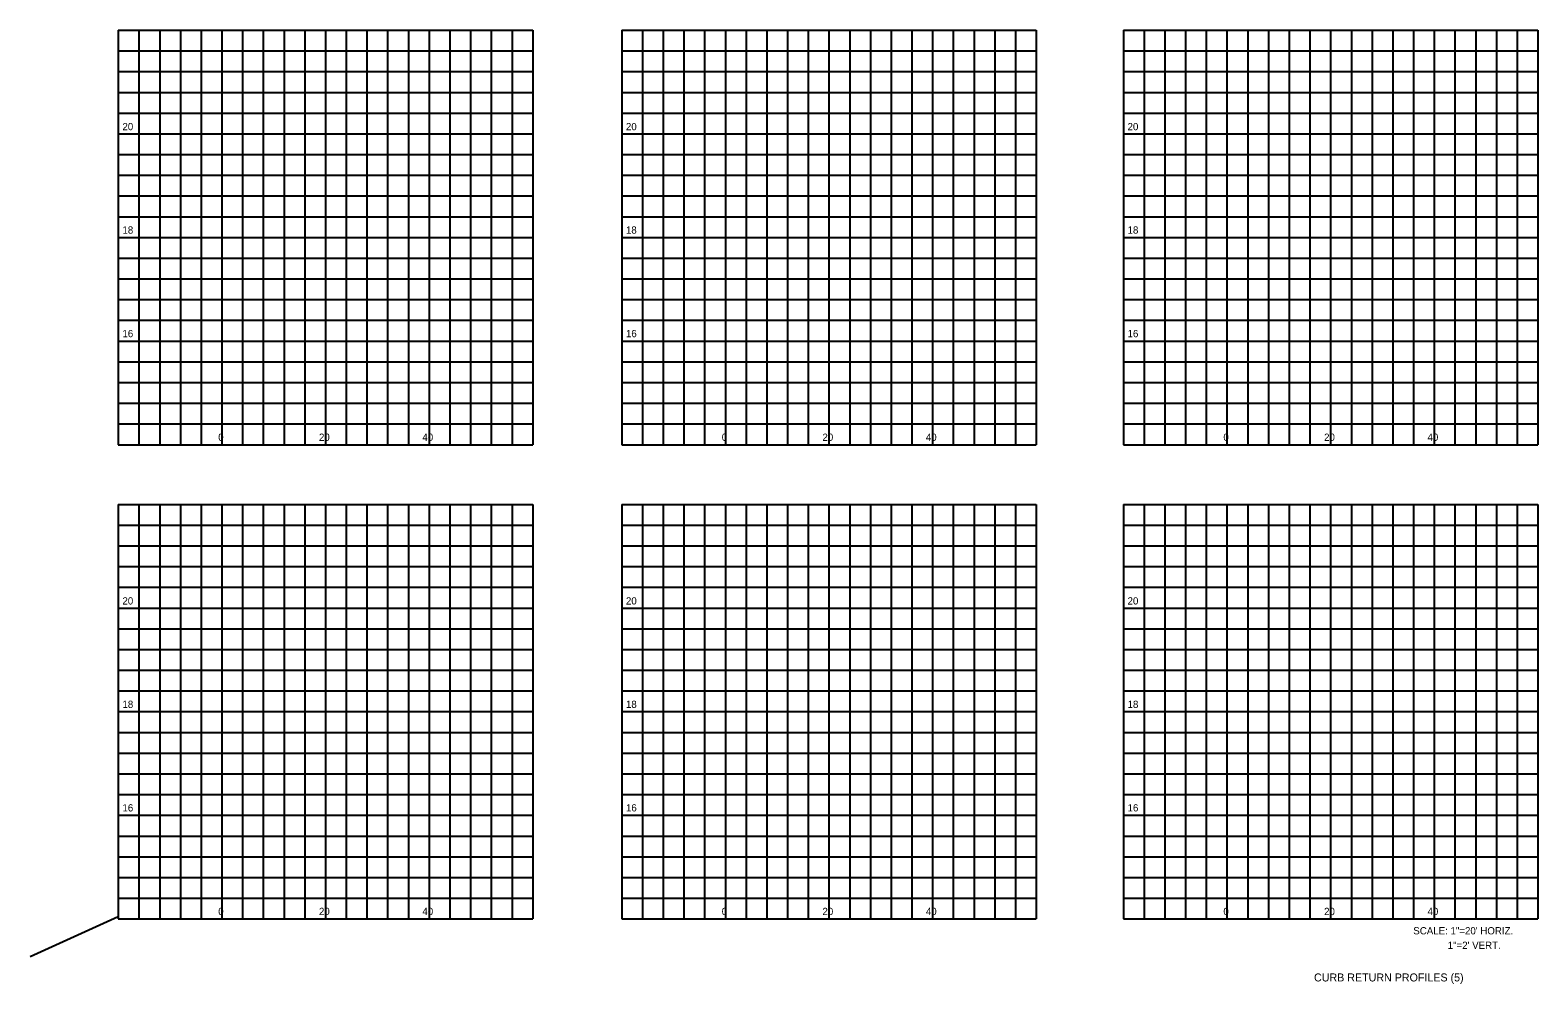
# Model space of a CAD drawing. Extents: x 127723 to 128378, y 21426 to 23736.
# Drawn here: x 127722.5 to 128013.5, y 22276.1 to 22460.2 of the extents above; entities that cross this region are included whole.
import ezdxf

# ---------------------------------------------------------------- set-up
doc = ezdxf.new("R2010")
doc.units = 0
for name, color, linetype in [('Default', 7, 'Continuous'), ('GroundCover', 7, 'Continuous'), ('Miscellaneous0', 7, 'Continuous'), ('SheetBorder_dp', 7, 'Continuous'), ('TextNotes', 7, 'Continuous')]:
    doc.layers.add(name, color=color, linetype=linetype)

msp = doc.modelspace()

# ---------------------------------------------------------------- linework, layer by layer
at = {"layer": 'Miscellaneous0'}
for p, q in [((127743.54, 22460.15), (127743.54, 22380.15)), ((127747.54, 22460.15), (127747.54, 22380.15)), ((127751.54, 22460.15), (127751.54, 22380.15)), ((127755.54, 22460.15), (127755.54, 22380.15)), ((127763.54, 22460.15), (127763.54, 22380.15)), ((127767.54, 22460.15), (127767.54, 22380.15)), ((127771.54, 22460.15), (127771.54, 22380.15)), ((127775.54, 22460.15), (127775.54, 22380.15)), ((127783.54, 22460.15), (127783.54, 22380.15)), ((127787.54, 22460.15), (127787.54, 22380.15)), ((127791.54, 22460.15), (127791.54, 22380.15)), ((127795.54, 22460.15), (127795.54, 22380.15)), ((127803.54, 22460.15), (127803.54, 22380.15)), ((127807.54, 22460.15), (127807.54, 22380.15)), ((127811.54, 22460.15), (127811.54, 22380.15)), ((127815.54, 22460.15), (127815.54, 22380.15)), ((127840.72, 22460.15), (127840.72, 22380.15)), ((127844.72, 22460.15), (127844.72, 22380.15)), ((127848.72, 22460.15), (127848.72, 22380.15)), ((127852.72, 22460.15), (127852.72, 22380.15)), ((127860.72, 22460.15), (127860.72, 22380.15)), ((127864.72, 22460.15), (127864.72, 22380.15)), ((127868.72, 22460.15), (127868.72, 22380.15)), ((127872.72, 22460.15), (127872.72, 22380.15)), ((127880.72, 22460.15), (127880.72, 22380.15)), ((127884.72, 22460.15), (127884.72, 22380.15)), ((127888.72, 22460.15), (127888.72, 22380.15)), ((127892.72, 22460.15), (127892.72, 22380.15)), ((127900.72, 22460.15), (127900.72, 22380.15)), ((127904.72, 22460.15), (127904.72, 22380.15)), ((127908.72, 22460.15), (127908.72, 22380.15)), ((127912.72, 22460.15), (127912.72, 22380.15)), ((127937.54, 22460.15), (127937.54, 22380.15)), ((127941.54, 22460.15), (127941.54, 22380.15)), ((127945.54, 22460.15), (127945.54, 22380.15)), ((127949.54, 22460.15), (127949.54, 22380.15)), ((127957.54, 22460.15), (127957.54, 22380.15)), ((127961.54, 22460.15), (127961.54, 22380.15)), ((127965.54, 22460.15), (127965.54, 22380.15)), ((127969.54, 22460.15), (127969.54, 22380.15)), ((127977.54, 22460.15), (127977.54, 22380.15)), ((127981.54, 22460.15), (127981.54, 22380.15)), ((127985.54, 22460.15), (127985.54, 22380.15)), ((127989.54, 22460.15), (127989.54, 22380.15)), ((127997.54, 22460.15), (127997.54, 22380.15)), ((128001.54, 22460.15), (128001.54, 22380.15)), ((128005.54, 22460.15), (128005.54, 22380.15)), ((128009.54, 22460.15), (128009.54, 22380.15)), ((127739.54, 22456.15), (127819.54, 22456.15)), ((127836.72, 22456.15), (127916.72, 22456.15)), ((127933.54, 22456.15), (128013.54, 22456.15)), ((127739.54, 22452.15), (127819.54, 22452.15)), ((127836.72, 22452.15), (127916.72, 22452.15)), ((127933.54, 22452.15), (128013.54, 22452.15)), ((127739.54, 22448.15), (127819.54, 22448.15)), ((127836.72, 22448.15), (127916.72, 22448.15)), ((127933.54, 22448.15), (128013.54, 22448.15)), ((127739.54, 22444.15), (127819.54, 22444.15)), ((127836.72, 22444.15), (127916.72, 22444.15)), ((127933.54, 22444.15), (128013.54, 22444.15)), ((127739.54, 22436.15), (127819.54, 22436.15)), ((127836.72, 22436.15), (127916.72, 22436.15)), ((127933.54, 22436.15), (128013.54, 22436.15)), ((127739.54, 22432.15), (127819.54, 22432.15)), ((127836.72, 22432.15), (127916.72, 22432.15)), ((127933.54, 22432.15), (128013.54, 22432.15)), ((127739.54, 22428.15), (127819.54, 22428.15)), ((127836.72, 22428.15), (127916.72, 22428.15)), ((127933.54, 22428.15), (128013.54, 22428.15)), ((127739.54, 22424.15), (127819.54, 22424.15)), ((127836.72, 22424.15), (127916.72, 22424.15)), ((127933.54, 22424.15), (128013.54, 22424.15)), ((127739.54, 22416.15), (127819.54, 22416.15)), ((127836.72, 22416.15), (127916.72, 22416.15)), ((127933.54, 22416.15), (128013.54, 22416.15)), ((127739.54, 22412.15), (127819.54, 22412.15)), ((127836.72, 22412.15), (127916.72, 22412.15)), ((127933.54, 22412.15), (128013.54, 22412.15)), ((127739.54, 22408.15), (127819.54, 22408.15)), ((127836.72, 22408.15), (127916.72, 22408.15)), ((127933.54, 22408.15), (128013.54, 22408.15)), ((127739.54, 22404.15), (127819.54, 22404.15)), ((127836.72, 22404.15), (127916.72, 22404.15)), ((127933.54, 22404.15), (128013.54, 22404.15)), ((127739.54, 22396.15), (127819.54, 22396.15)), ((127836.72, 22396.15), (127916.72, 22396.15)), ((127933.54, 22396.15), (128013.54, 22396.15)), ((127739.54, 22392.15), (127819.54, 22392.15)), ((127836.72, 22392.15), (127916.72, 22392.15)), ((127933.54, 22392.15), (128013.54, 22392.15)), ((127739.54, 22388.15), (127819.54, 22388.15)), ((127836.72, 22388.15), (127916.72, 22388.15)), ((127933.54, 22388.15), (128013.54, 22388.15)), ((127739.54, 22384.15), (127819.54, 22384.15)), ((127836.72, 22384.15), (127916.72, 22384.15)), ((127933.54, 22384.15), (128013.54, 22384.15)), ((127743.54, 22368.62), (127743.54, 22288.62)), ((127747.54, 22368.62), (127747.54, 22288.62)), ((127751.54, 22368.62), (127751.54, 22288.62)), ((127755.54, 22368.62), (127755.54, 22288.62)), ((127763.54, 22368.62), (127763.54, 22288.62)), ((127767.54, 22368.62), (127767.54, 22288.62)), ((127771.54, 22368.62), (127771.54, 22288.62)), ((127775.54, 22368.62), (127775.54, 22288.62)), ((127783.54, 22368.62), (127783.54, 22288.62)), ((127787.54, 22368.62), (127787.54, 22288.62)), ((127791.54, 22368.62), (127791.54, 22288.62)), ((127795.54, 22368.62), (127795.54, 22288.62)), ((127803.54, 22368.62), (127803.54, 22288.62)), ((127807.54, 22368.62), (127807.54, 22288.62)), ((127811.54, 22368.62), (127811.54, 22288.62)), ((127815.54, 22368.62), (127815.54, 22288.62)), ((127840.72, 22368.62), (127840.72, 22288.62)), ((127844.72, 22368.62), (127844.72, 22288.62)), ((127848.72, 22368.62), (127848.72, 22288.62)), ((127852.72, 22368.62), (127852.72, 22288.62)), ((127860.72, 22368.62), (127860.72, 22288.62)), ((127864.72, 22368.62), (127864.72, 22288.62)), ((127868.72, 22368.62), (127868.72, 22288.62)), ((127872.72, 22368.62), (127872.72, 22288.62)), ((127880.72, 22368.62), (127880.72, 22288.62)), ((127884.72, 22368.62), (127884.72, 22288.62)), ((127888.72, 22368.62), (127888.72, 22288.62)), ((127892.72, 22368.62), (127892.72, 22288.62)), ((127900.72, 22368.62), (127900.72, 22288.62)), ((127904.72, 22368.62), (127904.72, 22288.62)), ((127908.72, 22368.62), (127908.72, 22288.62)), ((127912.72, 22368.62), (127912.72, 22288.62)), ((127937.54, 22368.62), (127937.54, 22288.62)), ((127941.54, 22368.62), (127941.54, 22288.62)), ((127945.54, 22368.62), (127945.54, 22288.62)), ((127949.54, 22368.62), (127949.54, 22288.62)), ((127957.54, 22368.62), (127957.54, 22288.62)), ((127961.54, 22368.62), (127961.54, 22288.62)), ((127965.54, 22368.62), (127965.54, 22288.62)), ((127969.54, 22368.62), (127969.54, 22288.62)), ((127977.54, 22368.62), (127977.54, 22288.62)), ((127981.54, 22368.62), (127981.54, 22288.62)), ((127985.54, 22368.62), (127985.54, 22288.62)), ((127989.54, 22368.62), (127989.54, 22288.62)), ((127997.54, 22368.62), (127997.54, 22288.62)), ((128001.54, 22368.62), (128001.54, 22288.62)), ((128005.54, 22368.62), (128005.54, 22288.62)), ((128009.54, 22368.62), (128009.54, 22288.62)), ((127739.54, 22364.62), (127819.54, 22364.62)), ((127836.72, 22364.62), (127916.72, 22364.62)), ((127933.54, 22364.62), (128013.54, 22364.62)), ((127739.54, 22360.62), (127819.54, 22360.62)), ((127836.72, 22360.62), (127916.72, 22360.62)), ((127933.54, 22360.62), (128013.54, 22360.62)), ((127739.54, 22356.62), (127819.54, 22356.62)), ((127836.72, 22356.62), (127916.72, 22356.62)), ((127933.54, 22356.62), (128013.54, 22356.62)), ((127739.54, 22352.62), (127819.54, 22352.62)), ((127836.72, 22352.62), (127916.72, 22352.62)), ((127933.54, 22352.62), (128013.54, 22352.62)), ((127739.54, 22344.62), (127819.54, 22344.62)), ((127836.72, 22344.62), (127916.72, 22344.62)), ((127933.54, 22344.62), (128013.54, 22344.62)), ((127739.54, 22340.62), (127819.54, 22340.62)), ((127836.72, 22340.62), (127916.72, 22340.62)), ((127933.54, 22340.62), (128013.54, 22340.62)), ((127739.54, 22336.62), (127819.54, 22336.62)), ((127836.72, 22336.62), (127916.72, 22336.62)), ((127933.54, 22336.62), (128013.54, 22336.62)), ((127739.54, 22332.62), (127819.54, 22332.62)), ((127836.72, 22332.62), (127916.72, 22332.62)), ((127933.54, 22332.62), (128013.54, 22332.62)), ((127739.54, 22324.62), (127819.54, 22324.62)), ((127836.72, 22324.62), (127916.72, 22324.62)), ((127933.54, 22324.62), (128013.54, 22324.62)), ((127739.54, 22320.62), (127819.54, 22320.62)), ((127836.72, 22320.62), (127916.72, 22320.62)), ((127933.54, 22320.62), (128013.54, 22320.62)), ((127739.54, 22316.62), (127819.54, 22316.62)), ((127836.72, 22316.62), (127916.72, 22316.62)), ((127933.54, 22316.62), (128013.54, 22316.62)), ((127739.54, 22312.62), (127819.54, 22312.62)), ((127836.72, 22312.62), (127916.72, 22312.62)), ((127933.54, 22312.62), (128013.54, 22312.62)), ((127739.54, 22304.62), (127819.54, 22304.62)), ((127836.72, 22304.62), (127916.72, 22304.62)), ((127933.54, 22304.62), (128013.54, 22304.62)), ((127739.54, 22300.62), (127819.54, 22300.62)), ((127836.72, 22300.62), (127916.72, 22300.62)), ((127933.54, 22300.62), (128013.54, 22300.62)), ((127739.54, 22296.62), (127819.54, 22296.62)), ((127836.72, 22296.62), (127916.72, 22296.62)), ((127933.54, 22296.62), (128013.54, 22296.62)), ((127739.54, 22292.62), (127819.54, 22292.62)), ((127836.72, 22292.62), (127916.72, 22292.62)), ((127933.54, 22292.62), (128013.54, 22292.62))]:
    msp.add_line(p, q, dxfattribs=at)
at = {"layer": 'SheetBorder_dp'}
for p, q in [((127739.54, 22460.15), (127819.54, 22460.15)), ((127739.54, 22460.15), (127739.54, 22380.15)), ((127759.54, 22460.15), (127759.54, 22400.15)), ((127759.54, 22460.15), (127759.54, 22380.15)), ((127779.54, 22460.15), (127779.54, 22380.15)), ((127799.54, 22460.15), (127799.54, 22380.15)), ((127819.54, 22460.15), (127819.54, 22380.15)), ((127836.72, 22460.15), (127916.72, 22460.15)), ((127836.72, 22460.15), (127836.72, 22380.15)), ((127856.72, 22460.15), (127856.72, 22400.15)), ((127856.72, 22460.15), (127856.72, 22380.15)), ((127876.72, 22460.15), (127876.72, 22380.15)), ((127896.72, 22460.15), (127896.72, 22380.15)), ((127916.72, 22460.15), (127916.72, 22380.15)), ((127933.54, 22460.15), (128013.54, 22460.15)), ((127933.54, 22460.15), (127933.54, 22380.15)), ((127953.54, 22460.15), (127953.54, 22400.15)), ((127953.54, 22460.15), (127953.54, 22380.15)), ((127973.54, 22460.15), (127973.54, 22380.15)), ((127993.54, 22460.15), (127993.54, 22380.15)), ((128013.54, 22460.15), (128013.54, 22380.15)), ((127739.54, 22440.15), (127819.54, 22440.15)), ((127836.72, 22440.15), (127916.72, 22440.15)), ((127933.54, 22440.15), (128013.54, 22440.15)), ((127739.54, 22420.15), (127819.54, 22420.15)), ((127836.72, 22420.15), (127916.72, 22420.15)), ((127933.54, 22420.15), (128013.54, 22420.15)), ((127739.54, 22400.15), (127819.54, 22400.15)), ((127739.54, 22400.15), (127819.54, 22400.15)), ((127836.72, 22400.15), (127916.72, 22400.15)), ((127836.72, 22400.15), (127916.72, 22400.15)), ((127933.54, 22400.15), (128013.54, 22400.15)), ((127933.54, 22400.15), (128013.54, 22400.15)), ((127739.54, 22380.15), (127819.54, 22380.15)), ((127836.72, 22380.15), (127916.72, 22380.15)), ((127933.54, 22380.15), (128013.54, 22380.15)), ((127739.54, 22368.62), (127819.54, 22368.62)), ((127739.54, 22368.62), (127739.54, 22288.62)), ((127759.54, 22368.62), (127759.54, 22308.62)), ((127759.54, 22368.62), (127759.54, 22288.62)), ((127779.54, 22368.62), (127779.54, 22288.62)), ((127799.54, 22368.62), (127799.54, 22288.62)), ((127819.54, 22368.62), (127819.54, 22288.62)), ((127836.72, 22368.62), (127916.72, 22368.62)), ((127836.72, 22368.62), (127836.72, 22288.62)), ((127856.72, 22368.62), (127856.72, 22308.62)), ((127856.72, 22368.62), (127856.72, 22288.62)), ((127876.72, 22368.62), (127876.72, 22288.62)), ((127896.72, 22368.62), (127896.72, 22288.62)), ((127916.72, 22368.62), (127916.72, 22288.62)), ((127933.54, 22368.62), (128013.54, 22368.62)), ((127933.54, 22368.62), (127933.54, 22288.62)), ((127953.54, 22368.62), (127953.54, 22308.62)), ((127953.54, 22368.62), (127953.54, 22288.62)), ((127973.54, 22368.62), (127973.54, 22288.62)), ((127993.54, 22368.62), (127993.54, 22288.62)), ((128013.54, 22368.62), (128013.54, 22288.62)), ((127739.54, 22348.62), (127819.54, 22348.62)), ((127836.72, 22348.62), (127916.72, 22348.62)), ((127933.54, 22348.62), (128013.54, 22348.62)), ((127739.54, 22328.62), (127819.54, 22328.62)), ((127836.72, 22328.62), (127916.72, 22328.62)), ((127933.54, 22328.62), (128013.54, 22328.62)), ((127739.54, 22308.62), (127819.54, 22308.62)), ((127739.54, 22308.62), (127819.54, 22308.62)), ((127836.72, 22308.62), (127916.72, 22308.62)), ((127836.72, 22308.62), (127916.72, 22308.62)), ((127933.54, 22308.62), (128013.54, 22308.62)), ((127933.54, 22308.62), (128013.54, 22308.62)), ((127739.54, 22288.62), (127819.54, 22288.62)), ((127836.72, 22288.62), (127916.72, 22288.62)), ((127933.54, 22288.62), (128013.54, 22288.62))]:
    msp.add_line(p, q, dxfattribs=at)
at = {"layer": 'TextNotes'}
msp.add_line((127739.54, 22289), (127722.54, 22281.33), dxfattribs=at)

# ---------------------------------------------------------------- texts
at = {"layer": 'Default'}
msp.add_text('CURB RETURN PROFILES (5)', height=1.5418, dxfattribs=at).set_placement((127970.34, 22276.55))
at = {"layer": 'GroundCover'}
for s, p in [('20', (127740.35, 22440.84)), ('20', (127837.53, 22440.84)), ('20', (127934.35, 22440.84)), ('18', (127740.35, 22420.88)), ('18', (127837.53, 22420.88)), ('18', (127934.35, 22420.88)), ('16', (127740.35, 22400.89)), ('16', (127837.53, 22400.89)), ('16', (127934.35, 22400.89)), ('0', (127758.84, 22380.89)), ('20', (127778.28, 22380.89)), ('40', (127798.24, 22380.89)), ('0', (127856.02, 22380.89)), ('20', (127875.46, 22380.89)), ('40', (127895.42, 22380.89)), ('0', (127952.84, 22380.89)), ('20', (127972.28, 22380.89)), ('40', (127992.24, 22380.89)), ('20', (127740.35, 22349.3)), ('20', (127837.53, 22349.3)), ('20', (127934.35, 22349.3)), ('18', (127740.35, 22329.34)), ('18', (127837.53, 22329.34)), ('18', (127934.35, 22329.34)), ('16', (127740.35, 22309.36)), ('16', (127837.53, 22309.36)), ('16', (127934.35, 22309.36)), ('0', (127758.84, 22289.36)), ('20', (127778.28, 22289.36)), ('40', (127798.24, 22289.36)), ('0', (127856.02, 22289.36)), ('20', (127875.46, 22289.36)), ('40', (127895.42, 22289.36)), ('0', (127952.84, 22289.36)), ('20', (127972.28, 22289.36)), ('40', (127992.24, 22289.36)), ('SCALE: 1"=20\' HORIZ.', (127989.5, 22285.63)), ('  1"=2\' VERT.', (127995.1, 22282.83))]:
    msp.add_text(s, height=1.4, dxfattribs=at).set_placement(p)

doc.saveas('drawing.dxf')
